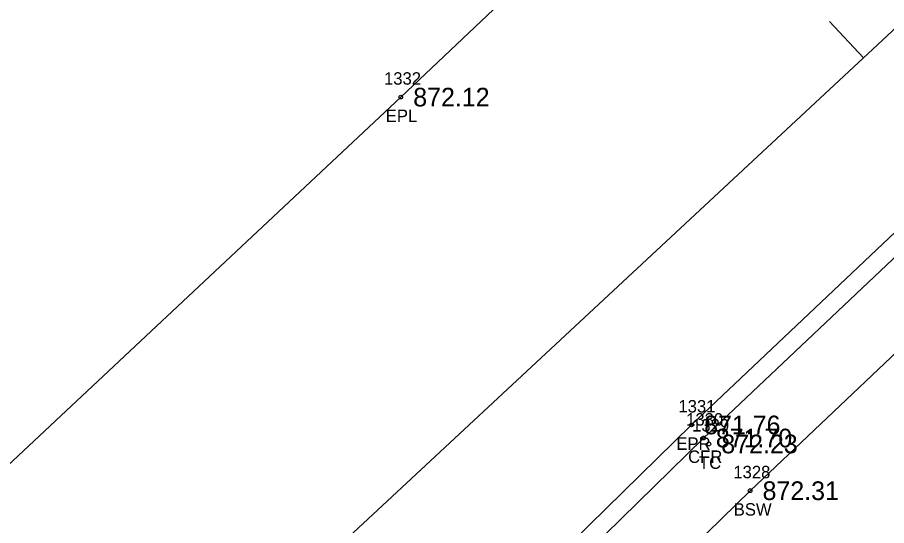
# Model space of a CAD drawing. Extents: x 1622501 to 1626664, y 1117816 to 1121579.
# Drawn here: x 1623774.2 to 1623844.1, y 1119083.8 to 1119124.7 of the extents above; entities that cross this region are included whole.
import ezdxf

# ---------------------------------------------------------------- set-up
doc = ezdxf.new("R2010")
doc.units = 0
for name, color, linetype in [('RD_EX_Conc', 7, 'Continuous'), ('RD_EX_Conc_txCode', 7, 'Continuous'), ('RD_EX_Road', 7, 'Continuous'), ('RD_EX_Road_txCode', 7, 'Continuous'), ('RD_EX_TX_Conc_ELEV', 7, 'Continuous'), ('RD_EX_TX_Road_ELEV', 7, 'Continuous'), ('RD_HC_Cl', 7, 'Continuous'), ('RD_HC_Data_Tic', 7, 'Continuous'), ('RD_SMD_Locator', 7, 'Continuous')]:
    doc.layers.add(name, color=color, linetype=linetype)

msp = doc.modelspace()

# ---------------------------------------------------------------- linework, layer by layer
at = {"layer": 'RD_EX_Conc'}
for points in [[(1623723.663, 1118851.276), (1623685.686, 1118891.781), (1623680.278, 1118899.276), (1623678.543, 1118902.667), (1623678.543, 1118902.667), (1623675.573, 1118911.952), (1623675.054, 1118920.354), (1623676.566, 1118930.331), (1623679.225, 1118937.184), (1623684.435, 1118944.641), (1623689.976, 1118950.418), (1623724.501, 1118984.8), (1623759.009, 1119020.42), (1623793.698, 1119055.906), (1623829.35, 1119090.862), (1623865.612, 1119125.129), (1623901.916, 1119159.181), (1623933.224, 1119188.498)], [(1623676.299, 1118912.014), (1623681.213, 1118913.011), (1623680.576, 1118920.41), (1623681.86, 1118928.773), (1623684.243, 1118934.734), (1623688.548, 1118940.788), (1623694.147, 1118946.67), (1623728.265, 1118980.628), (1623762.622, 1119016.068), (1623797.565, 1119051.919), (1623833.104, 1119086.631), (1623869.148, 1119120.8), (1623905.547, 1119154.999), (1623936.969, 1119184.346), (1623933.79, 1119188.026)]]:
    msp.add_lwpolyline(points, dxfattribs=at)
at = {"layer": 'RD_EX_Road'}
for points in [[(1623722.97, 1118850.612), (1623684.945, 1118891.225), (1623679.413, 1118898.675), (1623674.261, 1118911.526), (1623673.503, 1118920.185), (1623675.206, 1118930.826), (1623677.985, 1118937.822), (1623683.61, 1118945.518), (1623688.806, 1118951.265), (1623723.469, 1118985.717), (1623758.003, 1119021.43), (1623792.693, 1119056.92), (1623828.408, 1119091.915), (1623864.599, 1119126.191), (1623900.882, 1119160.216), (1623932.37, 1119189.416), (1623932.628, 1119189.219), (1623935.818, 1119192.17), (1623973.771, 1119227.767), (1623990.875, 1119243.538), (1624009.987, 1119262.018), (1624046.295, 1119296.153)], [(1623613.186, 1119042.019), (1623611.006, 1119043.814), (1623608.999, 1119042.947), (1623599.734, 1119032.628), (1623594.943, 1119023.41), (1623593.061, 1119016.814), (1623592.292, 1119005.793), (1623594.792, 1118992.799), (1623599.513, 1118985.89), (1623605.793, 1118978.903), (1623613.538, 1118973.355), (1623625.909, 1118968.984), (1623636.836, 1118968.46), (1623647.743, 1118971.195), (1623659.463, 1118979.46), (1623658.889, 1118980.17), (1623658.337, 1118980.438), (1623666.316, 1118985.506), (1623695.703, 1119013.851), (1623731.996, 1119048.998), (1623767.021, 1119082.64), (1623805.037, 1119118.246), (1623840.273, 1119151.616), (1623856.194, 1119167.062)]]:
    msp.add_lwpolyline(points, dxfattribs=at)
at = {"layer": 'RD_HC_Cl'}
msp.add_line((1623608.837, 1118904.32), (1623937.248, 1119209.793), dxfattribs=at)
at = {"layer": 'RD_HC_Data_Tic'}
msp.add_line((1623842.22, 1119121.402), (1623839.496, 1119124.331), dxfattribs=at)
at = {"layer": 'RD_SMD_Locator'}
for centre in [(1623805.037, 1119118.246), (1623828.408, 1119091.915), (1623829.35, 1119090.862), (1623829.792, 1119090.387), (1623833.104, 1119086.631)]:
    msp.add_circle(centre, 0.15, dxfattribs=at)

# ---------------------------------------------------------------- texts
at = {"layer": 'RD_EX_Conc_txCode'}
for s, p in [('1330', (1623827.964, 1119091.862)), ('1329', (1623828.445, 1119091.387)), ('CFR', (1623828.122, 1119088.862)), ('TC', (1623828.996, 1119088.387)), ('1328', (1623831.757, 1119087.631)), ('BSW', (1623831.789, 1119084.631))]:
    msp.add_text(s, height=1, dxfattribs=at).set_placement(p)
at = {"layer": 'RD_EX_Road_txCode'}
for s, p in [('1332', (1623803.69, 1119119.246)), ('EPL', (1623803.832, 1119116.246)), ('1331', (1623827.345, 1119092.915)), ('EPR', (1623827.179, 1119089.915))]:
    msp.add_text(s, height=1, dxfattribs=at).set_placement(p)
at = {"layer": 'RD_EX_TX_Conc_ELEV'}
for s, p in [('871.70', (1623830.35, 1119090.112)), ('872.23', (1623830.792, 1119089.637)), ('872.31', (1623834.104, 1119085.881))]:
    msp.add_text(s, height=1.5, dxfattribs=at).set_placement(p)
at = {"layer": 'RD_EX_TX_Road_ELEV'}
for s, p in [('872.12', (1623806.037, 1119117.496)), ('871.76', (1623829.408, 1119091.165))]:
    msp.add_text(s, height=1.5, dxfattribs=at).set_placement(p)

doc.saveas('drawing.dxf')
